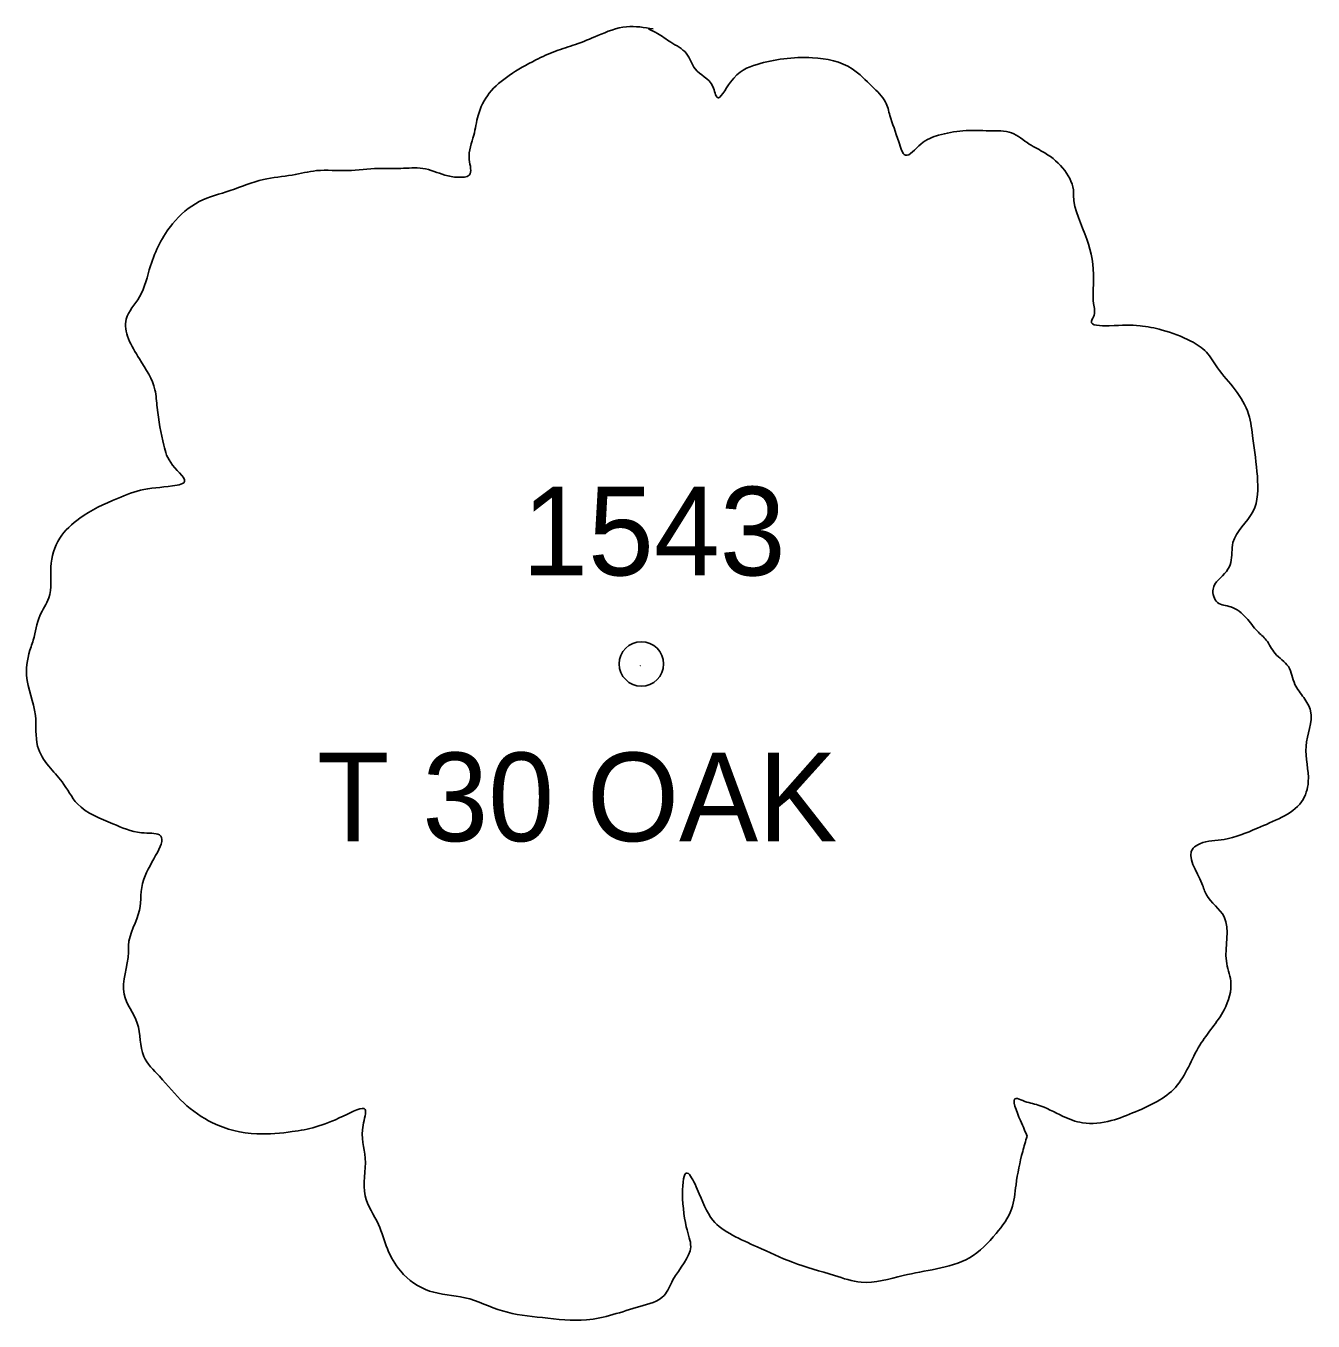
# Model space of a CAD drawing. Extents: x 1964982 to 1970452, y 1116335 to 1119906.
# Drawn here: x 1966495.85 to 1966510.38, y 1117519.43 to 1117534.05 of the extents above; entities that cross this region are included whole.
import ezdxf

# ---------------------------------------------------------------- set-up
doc = ezdxf.new("R2010")
doc.units = 0
doc.layers.add('RD_EX_VEG', color=7, linetype='Continuous')
doc.layers.add('RD_EX_VEG_txCode', color=7, linetype='Continuous')

msp = doc.modelspace()

# ---------------------------------------------------------------- linework, layer by layer
at = {"layer": 'RD_EX_VEG'}
for centre, radius in [((1966502.798, 1117526.851), 0.25), ((1966502.798, 1117526.851), 0.25), ((1966502.785, 1117526.832), 0.0001), ((1966502.785, 1117526.832), 0.0001)]:
    msp.add_circle(centre, radius, dxfattribs=at)
for points in [[(1966502.93, 1117534.018), (1966502.63, 1117534.043), (1966502.305, 1117533.943), (1966502.055, 1117533.843), (1966501.83, 1117533.768), (1966501.606, 1117533.668), (1966501.306, 1117533.493), (1966501.081, 1117533.293), (1966500.956, 1117533.043), (1966500.906, 1117532.819), (1966500.856, 1117532.544), (1966500.856, 1117532.369), (1966500.731, 1117532.344), (1966500.581, 1117532.369), (1966500.331, 1117532.444), (1966500.081, 1117532.444), (1966499.831, 1117532.444), (1966499.481, 1117532.419), (1966499.132, 1117532.419), (1966498.857, 1117532.369), (1966498.532, 1117532.319), (1966498.157, 1117532.194), (1966497.807, 1117532.069), (1966497.507, 1117531.819), (1966497.257, 1117531.344), (1966497.132, 1117530.994), (1966496.983, 1117530.744), (1966497.132, 1117530.295), (1966497.307, 1117529.945), (1966497.332, 1117529.745), (1966497.407, 1117529.32), (1966497.507, 1117529.095), (1966497.632, 1117528.895), (1966497.557, 1117528.87), (1966497.182, 1117528.82), (1966496.883, 1117528.72), (1966496.458, 1117528.495), (1966496.233, 1117528.271), (1966496.133, 1117527.946), (1966496.108, 1117527.596), (1966496.008, 1117527.396), (1966495.933, 1117527.121), (1966495.908, 1117527.046), (1966495.858, 1117526.721), (1966495.958, 1117526.271), (1966495.983, 1117525.922), (1966496.108, 1117525.697), (1966496.258, 1117525.522), (1966496.433, 1117525.272), (1966496.833, 1117525.047), (1966497.157, 1117524.947), (1966497.357, 1117524.922), (1966497.182, 1117524.422), (1966497.132, 1117524.072), (1966497.008, 1117523.673), (1966497.008, 1117523.598), (1966496.958, 1117523.123), (1966497.107, 1117522.798), (1966497.182, 1117522.423), (1966497.357, 1117522.198), (1966497.632, 1117521.898), (1966497.957, 1117521.673), (1966498.457, 1117521.548), (1966498.857, 1117521.573), (1966499.432, 1117521.748), (1966499.681, 1117521.823), (1966499.656, 1117521.648), (1966499.681, 1117521.274), (1966499.681, 1117520.849), (1966499.831, 1117520.524), (1966499.931, 1117520.249), (1966500.081, 1117519.999), (1966500.406, 1117519.774), (1966500.806, 1117519.699), (1966501.231, 1117519.549), (1966501.681, 1117519.474), (1966502.18, 1117519.449), (1966502.78, 1117519.599), (1966503.055, 1117519.724), (1966503.155, 1117519.899), (1966503.355, 1117520.274), (1966503.305, 1117520.499), (1966503.33, 1117521.099), (1966503.43, 1117520.924), (1966503.605, 1117520.574), (1966504.104, 1117520.274), (1966504.504, 1117520.099), (1966504.979, 1117519.949), (1966505.279, 1117519.874), (1966505.754, 1117519.949), (1966506.129, 1117520.024), (1966506.503, 1117520.149), (1966506.803, 1117520.424), (1966506.978, 1117520.699), (1966507.028, 1117520.974), (1966507.103, 1117521.349), (1966507.153, 1117521.523)], [(1966502.93, 1117534.018), (1966502.63, 1117534.043), (1966502.305, 1117533.943), (1966502.055, 1117533.843), (1966501.83, 1117533.768), (1966501.606, 1117533.668), (1966501.306, 1117533.493), (1966501.081, 1117533.293), (1966500.956, 1117533.043), (1966500.906, 1117532.819), (1966500.856, 1117532.544), (1966500.856, 1117532.369), (1966500.731, 1117532.344), (1966500.581, 1117532.369), (1966500.331, 1117532.444), (1966500.081, 1117532.444), (1966499.831, 1117532.444), (1966499.481, 1117532.419), (1966499.132, 1117532.419), (1966498.857, 1117532.369), (1966498.532, 1117532.319), (1966498.157, 1117532.194), (1966497.807, 1117532.069), (1966497.507, 1117531.819), (1966497.257, 1117531.344), (1966497.132, 1117530.994), (1966496.983, 1117530.744), (1966497.132, 1117530.295), (1966497.307, 1117529.945), (1966497.332, 1117529.745), (1966497.407, 1117529.32), (1966497.507, 1117529.095), (1966497.632, 1117528.895), (1966497.557, 1117528.87), (1966497.182, 1117528.82), (1966496.883, 1117528.72), (1966496.458, 1117528.495), (1966496.233, 1117528.271), (1966496.133, 1117527.946), (1966496.108, 1117527.596), (1966496.008, 1117527.396), (1966495.933, 1117527.121), (1966495.908, 1117527.046), (1966495.858, 1117526.721), (1966495.958, 1117526.271), (1966495.983, 1117525.922), (1966496.108, 1117525.697), (1966496.258, 1117525.522), (1966496.433, 1117525.272), (1966496.833, 1117525.047), (1966497.157, 1117524.947), (1966497.357, 1117524.922), (1966497.182, 1117524.422), (1966497.132, 1117524.072), (1966497.008, 1117523.673), (1966497.008, 1117523.598), (1966496.958, 1117523.123), (1966497.107, 1117522.798), (1966497.182, 1117522.423), (1966497.357, 1117522.198), (1966497.632, 1117521.898), (1966497.957, 1117521.673), (1966498.457, 1117521.548), (1966498.857, 1117521.573), (1966499.432, 1117521.748), (1966499.681, 1117521.823), (1966499.656, 1117521.648), (1966499.681, 1117521.274), (1966499.681, 1117520.849), (1966499.831, 1117520.524), (1966499.931, 1117520.249), (1966500.081, 1117519.999), (1966500.406, 1117519.774), (1966500.806, 1117519.699), (1966501.231, 1117519.549), (1966501.681, 1117519.474), (1966502.18, 1117519.449), (1966502.78, 1117519.599), (1966503.055, 1117519.724), (1966503.155, 1117519.899), (1966503.355, 1117520.274), (1966503.305, 1117520.499), (1966503.33, 1117521.099), (1966503.43, 1117520.924), (1966503.605, 1117520.574), (1966504.104, 1117520.274), (1966504.504, 1117520.099), (1966504.979, 1117519.949), (1966505.279, 1117519.874), (1966505.754, 1117519.949), (1966506.129, 1117520.024), (1966506.503, 1117520.149), (1966506.803, 1117520.424), (1966506.978, 1117520.699), (1966507.028, 1117520.974), (1966507.103, 1117521.349), (1966507.153, 1117521.523)], [(1966507.153, 1117521.523), (1966507.078, 1117521.698), (1966507.028, 1117521.948), (1966507.103, 1117521.923), (1966507.278, 1117521.873), (1966507.553, 1117521.748), (1966507.778, 1117521.673), (1966508.103, 1117521.698), (1966508.378, 1117521.798), (1966508.827, 1117522.073), (1966509.102, 1117522.548), (1966509.377, 1117522.948), (1966509.452, 1117523.273), (1966509.402, 1117523.498), (1966509.377, 1117523.997), (1966509.177, 1117524.247), (1966509.127, 1117524.372), (1966509.027, 1117524.772), (1966509.102, 1117524.822), (1966509.377, 1117524.872), (1966509.752, 1117524.997), (1966510.027, 1117525.122), (1966510.252, 1117525.297), (1966510.327, 1117525.522), (1966510.302, 1117525.922), (1966510.352, 1117526.321), (1966510.277, 1117526.471), (1966510.177, 1117526.621), (1966510.102, 1117526.821), (1966509.952, 1117526.971), (1966509.852, 1117527.121), (1966509.752, 1117527.221), (1966509.627, 1117527.371), (1966509.452, 1117527.496), (1966509.302, 1117527.546), (1966509.252, 1117527.696), (1966509.402, 1117527.896), (1966509.452, 1117527.996), (1966509.477, 1117528.221), (1966509.702, 1117528.57), (1966509.752, 1117528.97), (1966509.702, 1117529.395), (1966509.652, 1117529.67), (1966509.502, 1117529.945), (1966509.302, 1117530.195), (1966509.177, 1117530.37), (1966509.002, 1117530.495), (1966508.677, 1117530.62), (1966508.428, 1117530.669), (1966508.078, 1117530.669), (1966507.878, 1117530.719), (1966507.903, 1117530.769), (1966507.903, 1117530.919), (1966507.903, 1117531.194), (1966507.828, 1117531.644), (1966507.678, 1117532.144), (1966507.678, 1117532.169), (1966507.578, 1117532.419), (1966507.353, 1117532.619), (1966507.178, 1117532.719), (1966506.978, 1117532.844), (1966506.728, 1117532.869), (1966506.428, 1117532.869), (1966506.154, 1117532.819), (1966505.954, 1117532.719), (1966505.779, 1117532.594), (1966505.704, 1117532.744), (1966505.604, 1117533.043), (1966505.554, 1117533.193), (1966505.404, 1117533.368), (1966505.179, 1117533.568), (1966504.729, 1117533.693), (1966504.104, 1117533.618), (1966503.805, 1117533.418), (1966503.655, 1117533.243), (1966503.605, 1117533.368), (1966503.405, 1117533.568), (1966503.305, 1117533.743), (1966503.13, 1117533.868), (1966502.98, 1117533.968), (1966502.88, 1117534.018)], [(1966507.153, 1117521.523), (1966507.078, 1117521.698), (1966507.028, 1117521.948), (1966507.103, 1117521.923), (1966507.278, 1117521.873), (1966507.553, 1117521.748), (1966507.778, 1117521.673), (1966508.103, 1117521.698), (1966508.378, 1117521.798), (1966508.827, 1117522.073), (1966509.102, 1117522.548), (1966509.377, 1117522.948), (1966509.452, 1117523.273), (1966509.402, 1117523.498), (1966509.377, 1117523.997), (1966509.177, 1117524.247), (1966509.127, 1117524.372), (1966509.027, 1117524.772), (1966509.102, 1117524.822), (1966509.377, 1117524.872), (1966509.752, 1117524.997), (1966510.027, 1117525.122), (1966510.252, 1117525.297), (1966510.327, 1117525.522), (1966510.302, 1117525.922), (1966510.352, 1117526.321), (1966510.277, 1117526.471), (1966510.177, 1117526.621), (1966510.102, 1117526.821), (1966509.952, 1117526.971), (1966509.852, 1117527.121), (1966509.752, 1117527.221), (1966509.627, 1117527.371), (1966509.452, 1117527.496), (1966509.302, 1117527.546), (1966509.252, 1117527.696), (1966509.402, 1117527.896), (1966509.452, 1117527.996), (1966509.477, 1117528.221), (1966509.702, 1117528.57), (1966509.752, 1117528.97), (1966509.702, 1117529.395), (1966509.652, 1117529.67), (1966509.502, 1117529.945), (1966509.302, 1117530.195), (1966509.177, 1117530.37), (1966509.002, 1117530.495), (1966508.677, 1117530.62), (1966508.428, 1117530.669), (1966508.078, 1117530.669), (1966507.878, 1117530.719), (1966507.903, 1117530.769), (1966507.903, 1117530.919), (1966507.903, 1117531.194), (1966507.828, 1117531.644), (1966507.678, 1117532.144), (1966507.678, 1117532.169), (1966507.578, 1117532.419), (1966507.353, 1117532.619), (1966507.178, 1117532.719), (1966506.978, 1117532.844), (1966506.728, 1117532.869), (1966506.428, 1117532.869), (1966506.154, 1117532.819), (1966505.954, 1117532.719), (1966505.779, 1117532.594), (1966505.704, 1117532.744), (1966505.604, 1117533.043), (1966505.554, 1117533.193), (1966505.404, 1117533.368), (1966505.179, 1117533.568), (1966504.729, 1117533.693), (1966504.104, 1117533.618), (1966503.805, 1117533.418), (1966503.655, 1117533.243), (1966503.605, 1117533.368), (1966503.405, 1117533.568), (1966503.305, 1117533.743), (1966503.13, 1117533.868), (1966502.98, 1117533.968), (1966502.88, 1117534.018)]]:
    msp.add_spline(points, degree=3, dxfattribs=at)

# ---------------------------------------------------------------- texts
at = {"layer": 'RD_EX_VEG_txCode'}
for s, p in [('1543', (1966501.452, 1117527.851)), ('1543', (1966501.452, 1117527.851)), ('T 30 OAK', (1966499.137, 1117524.851)), ('T 30 OAK', (1966499.137, 1117524.851))]:
    msp.add_text(s, height=1, dxfattribs=at).set_placement(p)

doc.saveas('drawing.dxf')
